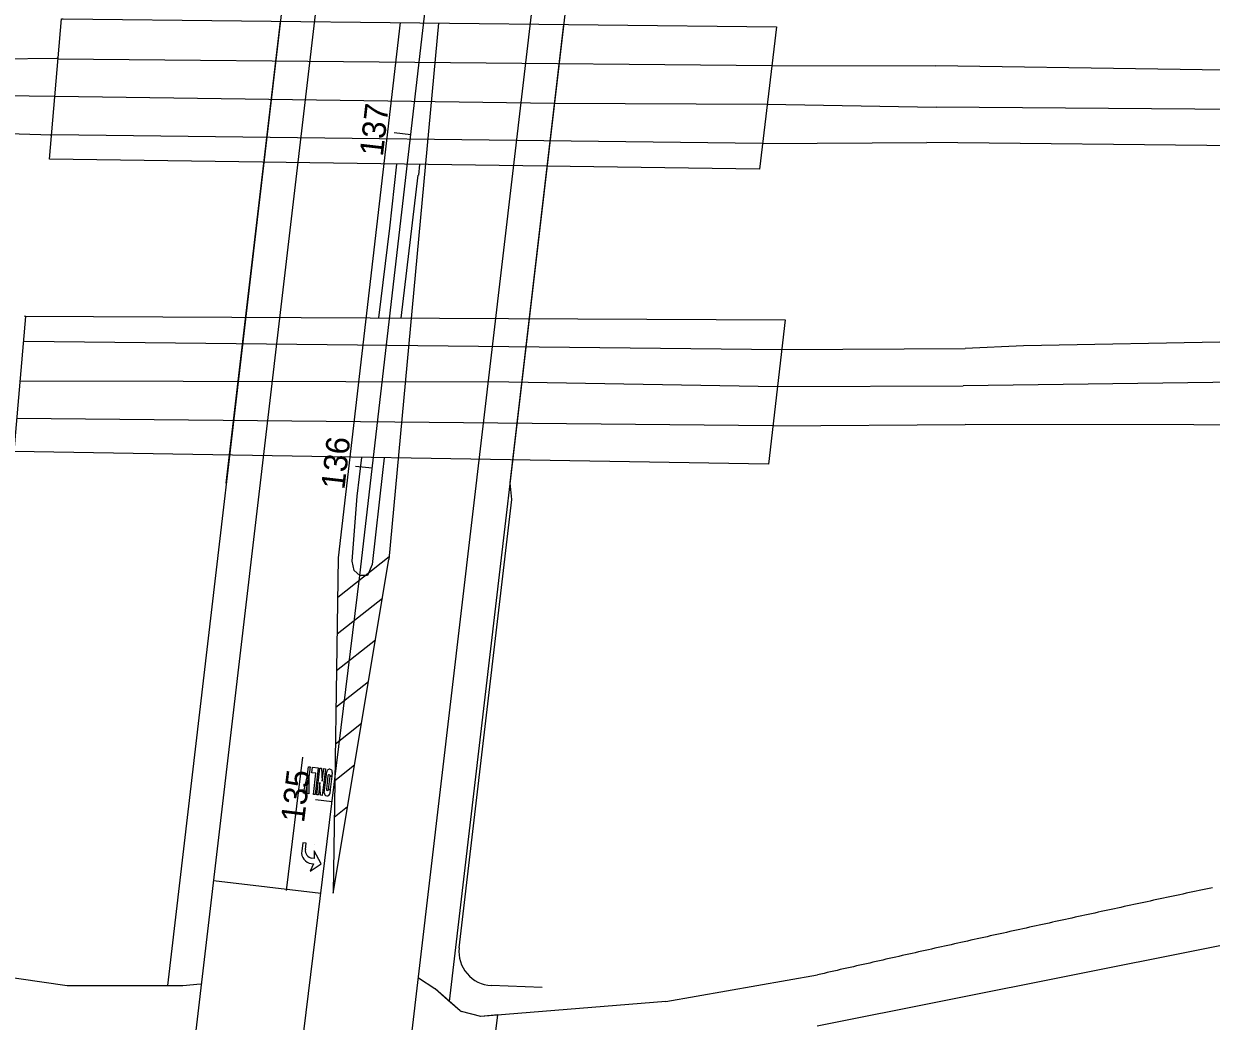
# Model space of a CAD drawing. Extents: x 2318076 to 2324211, y 613525 to 629939.
# Drawn here: x 2320472.4 to 2320826.1, y 628005.7 to 628302.7 of the extents above; entities that cross this region are included whole.
import ezdxf

# ---------------------------------------------------------------- set-up
doc = ezdxf.new("R2010")
doc.units = 0
for name, color, linetype in [('BR_X_Slab_Object', 7, 'Continuous'), ('GE_P_CL_50', 7, 'Continuous'), ('GE_X_CL_50', 7, 'Continuous'), ('PM_P_Cells', 7, 'Continuous'), ('PM_P_Channelizing_Line', 7, 'Continuous'), ('PM_P_CL_Double_Solid', 7, 'Continuous'), ('PM_P_Stop_Line', 7, 'Continuous'), ('PM_P_Transverse_Line', 7, 'Continuous'), ('PV_P_EOP', 7, 'Continuous'), ('PV_P_Shoulder', 7, 'Continuous'), ('RD_X_Concrete_Barrier', 7, 'Continuous'), ('RD_X_GR_Rt', 7, 'Continuous'), ('RS_Raster1', 7, 'Continuous'), ('TX_P_1', 7, 'Continuous')]:
    doc.layers.add(name, color=color, linetype=linetype)

msp = doc.modelspace()

# ---------------------------------------------------------------- linework, layer by layer
at = {"layer": 'BR_X_Slab_Object'}
for points in [[(2320484.11, 628304.16), (2320696.64, 628301.84), (2320691.49, 628259.41), (2320480.05, 628262.45), (2320483.63, 628304.22), (2320484.11, 628304.16)], [(2320472.62, 628215.62), (2320699.2, 628214.57), (2320694.19, 628171.55), (2320469.54, 628175.38), (2320473.07, 628215.6), (2320472.62, 628215.62)]]:
    msp.add_lwpolyline(points, dxfattribs=at)
at = {"layer": 'GE_P_CL_50'}
for p, q in [((2320587.68, 628269.7), (2320582.71, 628270.28)), ((2320576.2, 628170.36), (2320571.24, 628170.94)), ((2320564.24, 628071.08), (2320559.28, 628071.69))]:
    msp.add_line(p, q, dxfattribs=at)
msp.add_lwpolyline([(2320485.22, 627375.57), (2320502.11, 627520.92), (2320519.22, 627676.47), (2320531.82, 627783.89), (2320546.8, 627927.12), (2320554.45, 627991.34), (2320572.51, 628138.41), (2320649.52, 628804.84), (2320678.77, 629064.5), (2320690.76, 629163.78), (2320713.75, 629362.45), (2320725.26, 629461.78), (2320736.97, 629561.09), (2320748.4, 629660.43), (2320759.09, 629759.86), (2320769.62, 629859.3), (2320777.51, 629931.12), (2320778.25, 629937.84)], dxfattribs=at)
at = {"layer": 'GE_X_CL_50'}
for p, q in [((2320693.84, 628278.81), (2320744.17, 628277.94)), ((2320696.89, 628194.75), (2320752.2, 628194.93))]:
    msp.add_line(p, q, dxfattribs=at)
for points in [[(2318838.45, 628297.22), (2318989.13, 628295.38), (2319088.09, 628295.11), (2319168.95, 628294.58), (2319288.86, 628293.23), (2319411.65, 628291.27), (2319534.7, 628290.63), (2319653.02, 628288.28), (2319787.77, 628287.82), (2319899.47, 628286.31), (2320023.98, 628283.93), (2320152.65, 628284.01), (2320313.42, 628283.33), (2320481.66, 628281.19)], [(2320481.66, 628281.19), (2320630.42, 628279.04), (2320693.84, 628278.81)], [(2324211.2, 628237.88), (2324100.06, 628239.11), (2323887.64, 628240.84), (2323663.24, 628242.75), (2323428.01, 628246.39), (2323213.46, 628248.27), (2322983.92, 628250.37), (2322767.24, 628252.05), (2322547.46, 628255.46), (2322330.87, 628255.46), (2322180.02, 628258.17), (2321966.82, 628260.25), (2321752.93, 628261.56), (2321536.81, 628262.78), (2321340.76, 628266.62), (2321134.19, 628270.5), (2320911.42, 628276.64), (2320744.17, 628277.94)], [(2324209.54, 628169.05), (2324083.71, 628171.5), (2323932.07, 628172.99), (2323766.88, 628174.57), (2323590.27, 628175.99), (2323408.74, 628177.82), (2323205.61, 628179.86), (2322996.88, 628181.76), (2322795.55, 628183.99), (2322599.35, 628185.59), (2322419.03, 628185.84), (2322219.16, 628188.61), (2322096.17, 628189.9), (2321916.88, 628191.94), (2321753.71, 628193.94), (2321590.88, 628195.93), (2321431.73, 628197.42), (2321257.02, 628198.59), (2321067.83, 628197.06), (2320865.89, 628196.4), (2320752.2, 628194.93)], [(2320471.39, 628196.41), (2320616.88, 628196.07), (2320696.89, 628194.75)]]:
    msp.add_lwpolyline(points, dxfattribs=at)
at = {"layer": 'PM_P_Cells'}
for p, q in [((2320556.86, 628078.52), (2320557.21, 628081.5)), ((2320557.21, 628081.5), (2320557.71, 628081.44)), ((2320557.71, 628081.44), (2320557.36, 628078.46)), ((2320558.26, 628079.7), (2320558.46, 628081.35)), ((2320558.46, 628081.35), (2320560.11, 628081.16)), ((2320560.11, 628081.16), (2320559.16, 628073.21)), ((2320559.66, 628073.15), (2320560.61, 628081.1)), ((2320560.53, 628081.11), (2320560.53, 628081.11)), ((2320560.61, 628081.1), (2320561.1, 628081.04)), ((2320561.1, 628081.04), (2320561.32, 628077.24)), ((2320561.32, 628077.24), (2320561.77, 628080.96)), ((2320562.26, 628080.9), (2320561.32, 628072.96)), ((2320561.77, 628080.96), (2320562.26, 628080.9)), ((2320555.69, 628073.63), (2320556.86, 628078.52)), ((2320557.36, 628078.46), (2320557.34, 628073.43)), ((2320559.42, 628079.56), (2320558.26, 628079.7)), ((2320558.67, 628073.27), (2320559.42, 628079.56)), ((2320561.91, 628073.72), (2320562.66, 628080.01)), ((2320563.02, 628078.8), (2320562.55, 628074.82)), ((2320563.21, 628074.75), (2320563.68, 628078.72)), ((2320564.18, 628078.66), (2320563.68, 628078.72)), ((2320563.68, 628078.72), (2320564.18, 628078.66)), ((2320564.18, 628078.66), (2320563.7, 628074.69)), ((2320564.32, 628079.82), (2320564.18, 628078.66)), ((2320556.19, 628073.57), (2320555.69, 628073.63)), ((2320556.83, 628076.18), (2320556.19, 628073.57)), ((2320556.85, 628073.49), (2320556.83, 628076.18)), ((2320557.34, 628073.43), (2320556.85, 628073.49)), ((2320560.6, 628076.82), (2320560.16, 628073.09)), ((2320560.82, 628073.02), (2320560.6, 628076.82)), ((2320563.21, 628074.75), (2320563.7, 628074.69)), ((2320563.7, 628074.69), (2320563.21, 628074.75)), ((2320563.7, 628074.69), (2320563.57, 628073.53)), ((2320559.16, 628073.21), (2320558.67, 628073.27)), ((2320559.58, 628073.16), (2320559.58, 628073.16)), ((2320560.16, 628073.09), (2320559.66, 628073.15)), ((2320561.32, 628072.96), (2320560.82, 628073.02)), ((2320555.58, 628058.86), (2320555.21, 628056.41)), ((2320556.57, 628058.71), (2320555.58, 628058.86)), ((2320556.29, 628056.87), (2320556.57, 628058.71)), ((2320558.88, 628058.37), (2320558.88, 628058.37)), ((2320561.04, 628052.55), (2320558.92, 628056.42)), ((2320558.92, 628056.42), (2320558.92, 628054.16)), ((2320558.69, 628052.57), (2320557.7, 628050.45)), ((2320557.7, 628050.45), (2320561.04, 628052.55)), ((2320558.03, 628052.67), (2320558.69, 628052.57)), ((2320558.92, 628054.16), (2320558.23, 628054.26)), ((2320557.7, 628050.45), (2320557.7, 628050.45))]:
    msp.add_line(p, q, dxfattribs=at)
for centre, radius, start, end in [((2320563.49, 628079.92), 0.833, 353.2057, 173.2057), ((2320563.35, 628078.76), 0.333, 353.2057, 173.2057), ((2320562.74, 628073.63), 0.833, 173.2057, 353.2057), ((2320562.88, 628074.78), 0.333, 173.2057, 353.2057), ((2320558.46, 628055.92), 3.28, 171.5547, 262.4632), ((2320558.57, 628056.53), 2.3, 171.5547, 261.5547)]:
    msp.add_arc(centre, radius, start, end, dxfattribs=at)
at = {"layer": 'PM_P_Channelizing_Line'}
msp.add_lwpolyline([(2320550.68, 628044.66), (2320555.55, 628084.31)], dxfattribs=at)
at = {"layer": 'PM_P_CL_Double_Solid'}
for p, q in [((2320566.09, 628143.74), (2320564.56, 628043.85)), ((2320564.56, 628043.85), (2320581.17, 628143.24))]:
    msp.add_line(p, q, dxfattribs=at)
at = {"layer": 'PM_P_Stop_Line'}
msp.add_line((2320560.89, 628043.75), (2320528.92, 628047.49), dxfattribs=at)
at = {"layer": 'PM_P_Transverse_Line'}
for p, q in [((2320581.24, 628144), (2320565.91, 628131.86)), ((2320579.23, 628131.63), (2320565.74, 628120.95)), ((2320577.16, 628119.22), (2320565.58, 628110.05)), ((2320575.08, 628106.8), (2320565.41, 628099.14)), ((2320573.01, 628094.39), (2320565.24, 628088.24)), ((2320570.93, 628081.97), (2320565.07, 628077.33)), ((2320568.85, 628069.56), (2320564.9, 628066.43))]:
    msp.add_line(p, q, dxfattribs=at)
at = {"layer": 'PV_P_EOP'}
for p, q in [((2320590.74, 628574.92), (2320513.05, 627912.02)), ((2320576.7, 627905.37), (2320654.32, 628567.57)), ((2320584.51, 628303.06), (2320566.09, 628143.74)), ((2320595.94, 628302.94), (2320581.17, 628143.24)), ((2320594.89, 628015.41), (2320589.97, 628018.59)), ((2320602.43, 628008.79), (2320594.99, 628015.33)), ((2320608.54, 628007.18), (2320602.78, 628008.61)), ((2320613.63, 628007.58), (2320608.54, 628007.18))]:
    msp.add_line(p, q, dxfattribs=at)
msp.add_lwpolyline([(2320609.79, 627975.91), (2320611.27, 627988.34), (2320613.63, 628007.58)], dxfattribs=at)
for centre, start, end in [((2320594.44, 628014.71), 48.6772, 57.1121), ((2320602.98, 628009.42), 228.6772, 256.0413)]:
    msp.add_arc(centre, 0.833, start, end, dxfattribs=at)
at = {"layer": 'PV_P_Shoulder'}
for p, q in [((2320567.18, 628459.79), (2320515.22, 628016.39)), ((2320599.22, 628011.62), (2320651.77, 628459.98))]:
    msp.add_line(p, q, dxfattribs=at)
at = {"layer": 'RD_X_Concrete_Barrier'}
for p, q in [((2320532.74, 628165.9), (2320548.86, 628303.45)), ((2320617.32, 628166.06), (2320633.31, 628302.53)), ((2320590.26, 628260.87), (2320589.95, 628257.65)), ((2320589.78, 628257.63), (2320584.73, 628215.1))]:
    msp.add_line(p, q, dxfattribs=at)
for points in [[(2320578.2, 628215.13), (2320581.45, 628241.83), (2320583.5, 628260.96)], [(2320579.8, 628173.5), (2320579.27, 628169.07), (2320576.16, 628141.69), (2320574.82, 628138.47), (2320572.51, 628138.41), (2320570.8, 628139.9), (2320570.22, 628142.76), (2320571.74, 628162.06), (2320573.15, 628173.61)]]:
    msp.add_lwpolyline(points, dxfattribs=at)
at = {"layer": 'RD_X_GR_Rt'}
for p, q in [((2320617.74, 628161.06), (2320617.32, 628166.06)), ((2320602.09, 628027.57), (2320617.74, 628161.06)), ((2320626.8, 628015.81), (2320611.63, 628016.41))]:
    msp.add_line(p, q, dxfattribs=at)
msp.add_arc((2320612.03, 628026.4), 10, 173.3152, 267.7232, dxfattribs=at)
at = {"layer": 'RS_Raster1'}
for p, q in [((2320461.2, 628292.32), (2320482.62, 628292.44)), ((2320482.6, 628292.26), (2320695.24, 628290.34)), ((2320695.24, 628290.34), (2320743.98, 628290.21)), ((2320459.66, 628270.38), (2320480.66, 628269.62)), ((2320692.42, 628267.1), (2320480.67, 628269.63)), ((2320692.42, 628267.1), (2320741.34, 628267.39)), ((2320472.42, 628208.2), (2320698.17, 628205.7)), ((2320770.14, 628206.88), (2320752.78, 628205.99)), ((2320695.53, 628183.05), (2320470.4, 628185.22)), ((2320594.89, 628015.41), (2320590.03, 628018.55)), ((2320663.67, 628011.61), (2320708.82, 628019.53)), ((2320663.67, 628011.61), (2320608.54, 628007.18)), ((2320608.54, 628007.18), (2320602.78, 628008.61))]:
    msp.add_line(p, q, dxfattribs=at)
for points in [[(2321697.05, 628274.02), (2321509.24, 628275.49), (2321370.91, 628277.11), (2321223.2, 628279.67), (2321052.69, 628284.46), (2320876.34, 628288.23), (2320743.98, 628290.21)], [(2324210.96, 628226.01), (2324099.22, 628227.57), (2323922.84, 628229.43), (2323739.86, 628231.28), (2323551.5, 628233.43), (2323336.85, 628235.53), (2323118.39, 628237.8), (2322909.54, 628239.37), (2322678.89, 628242.27), (2322452.59, 628244.32), (2322252.25, 628245.65), (2322069.8, 628245.81), (2321869.81, 628248.03), (2321681.36, 628250.63), (2321451.01, 628251.29), (2321296.61, 628255.84), (2321123.18, 628260.35), (2320935.09, 628265.29), (2320741.34, 628267.39)], [(2324210.07, 628180.67), (2324126.99, 628181.82), (2323958.68, 628184.57), (2323765.72, 628185.78), (2323548.27, 628187.93), (2323298.91, 628189.99), (2323072.28, 628191.93), (2322817.32, 628194.08), (2322597.41, 628196.59), (2322367.08, 628198.37), (2322155.33, 628199.98), (2321962.28, 628202.76), (2321790.39, 628204.89), (2321604.43, 628210.03), (2321438.69, 628212.52), (2321272.37, 628212.78), (2321119.1, 628211.16), (2320939.43, 628209.93), (2320770.14, 628206.88)], [(2320698.17, 628205.7), (2320698.17, 628205.7), (2320752.83, 628205.99)], [(2319189.51, 628197.31), (2319278.1, 628191.01), (2319395.77, 628176.98), (2319442.58, 628171.23), (2319554.55, 628155.67), (2319664, 628139.56), (2319756.39, 628124.2), (2319834.01, 628113.24), (2319936.02, 628098.51), (2320027.26, 628084.66), (2320115.57, 628071.64), (2320199.48, 628059.37), (2320283.19, 628046.33), (2320384.46, 628030.93), (2320485.38, 628016.39)], [(2320695.53, 628183.05), (2320695.53, 628183.05), (2320752.78, 628183.39)], [(2321865.45, 628179.25), (2321679, 628181.71), (2321540.89, 628182.89), (2321384.45, 628185.57), (2321228.86, 628185.44), (2321052.77, 628183.94), (2320889, 628183.16), (2320752.78, 628183.39)], [(2321179.73, 628096.75), (2321032.45, 628067.95), (2320861.47, 628034.7), (2320708.68, 628004.26)], [(2320826.41, 628045.47), (2320825.44, 628045.27), (2320824.47, 628045.06), (2320823.49, 628044.85), (2320822.52, 628044.64), (2320821.55, 628044.44), (2320820.57, 628044.23), (2320819.6, 628044.02), (2320818.63, 628043.81), (2320817.65, 628043.6), (2320816.68, 628043.4), (2320815.71, 628043.19), (2320814.73, 628042.98), (2320813.76, 628042.77), (2320812.79, 628042.56), (2320811.81, 628042.35), (2320810.84, 628042.14), (2320809.87, 628041.93), (2320808.9, 628041.73), (2320807.92, 628041.52), (2320806.95, 628041.31), (2320805.98, 628041.1), (2320805, 628040.89), (2320804.03, 628040.68), (2320803.06, 628040.47), (2320802.09, 628040.26), (2320801.11, 628040.05), (2320800.14, 628039.84), (2320799.17, 628039.63), (2320798.19, 628039.42), (2320797.22, 628039.21), (2320796.25, 628038.99), (2320795.28, 628038.78), (2320794.3, 628038.57), (2320793.33, 628038.36), (2320792.36, 628038.15), (2320791.39, 628037.94), (2320790.41, 628037.73), (2320789.44, 628037.52), (2320788.47, 628037.3), (2320787.5, 628037.09), (2320786.52, 628036.88), (2320785.55, 628036.67), (2320784.58, 628036.46), (2320783.61, 628036.24), (2320782.63, 628036.03), (2320781.66, 628035.82), (2320780.69, 628035.61), (2320779.72, 628035.39), (2320778.75, 628035.18), (2320777.77, 628034.97), (2320776.8, 628034.75), (2320775.83, 628034.54), (2320774.86, 628034.33), (2320773.89, 628034.11), (2320772.91, 628033.9), (2320771.94, 628033.69), (2320770.97, 628033.47), (2320770, 628033.26), (2320769.03, 628033.04), (2320768.05, 628032.83), (2320767.08, 628032.61), (2320766.11, 628032.4), (2320765.14, 628032.19), (2320764.17, 628031.97), (2320763.19, 628031.76), (2320762.22, 628031.54), (2320761.25, 628031.33), (2320760.28, 628031.11), (2320759.31, 628030.89), (2320758.34, 628030.68), (2320757.36, 628030.46), (2320756.39, 628030.25), (2320755.42, 628030.03), (2320754.45, 628029.82), (2320753.48, 628029.6), (2320752.51, 628029.38), (2320751.54, 628029.17), (2320750.56, 628028.95), (2320749.59, 628028.73), (2320748.62, 628028.52), (2320747.65, 628028.3), (2320746.68, 628028.08), (2320745.71, 628027.87), (2320744.74, 628027.65), (2320743.77, 628027.43), (2320742.79, 628027.21), (2320741.82, 628027), (2320740.85, 628026.78), (2320739.88, 628026.56), (2320738.91, 628026.34), (2320737.94, 628026.13), (2320736.97, 628025.91), (2320736, 628025.69), (2320735.03, 628025.47), (2320734.05, 628025.25), (2320733.08, 628025.03), (2320732.11, 628024.82), (2320731.14, 628024.6), (2320730.17, 628024.38), (2320729.2, 628024.16), (2320728.23, 628023.94), (2320727.26, 628023.72), (2320726.29, 628023.5), (2320725.32, 628023.28), (2320724.35, 628023.06), (2320723.38, 628022.84), (2320722.41, 628022.62), (2320721.44, 628022.4), (2320720.46, 628022.18), (2320719.49, 628021.96), (2320718.52, 628021.74), (2320717.55, 628021.52), (2320716.58, 628021.3), (2320715.61, 628021.08), (2320714.64, 628020.86), (2320713.67, 628020.64), (2320712.7, 628020.42), (2320711.73, 628020.19), (2320710.76, 628019.97), (2320709.79, 628019.75), (2320708.82, 628019.53)], [(2320485.38, 628016.39), (2320494.26, 628016.39), (2320499.53, 628016.39), (2320508.04, 628016.39), (2320519.83, 628016.39), (2320525.1, 628016.85)], [(2320602.43, 628008.79), (2320598.76, 628012.02), (2320594.99, 628015.33)]]:
    msp.add_lwpolyline(points, dxfattribs=at)
for centre, start, end in [((2320594.44, 628014.71), 48.6772, 57.1121), ((2320602.98, 628009.42), 228.6772, 256.0413)]:
    msp.add_arc(centre, 0.833, start, end, dxfattribs=at)
at = {"layer": 'TX_P_1'}
for p, q in [((2320482.23, 628292.44), (2320482.62, 628292.44)), ((2320482.6, 628292.26), (2320482.32, 628292.44)), ((2320480.33, 628269.63), (2320480.67, 628269.63))]:
    msp.add_line(p, q, dxfattribs=at)

# ---------------------------------------------------------------- texts
at = {"layer": 'GE_P_CL_50'}
for s, rotation, p in [('137', 83.4084, (2320579.36, 628263.04)), ('136', 83.4084, (2320567.9, 628163.83)), ('135', 82.9992, (2320555.89, 628064.64))]:
    msp.add_text(s, height=7, rotation=rotation, dxfattribs=at).set_placement(p)

doc.saveas('drawing.dxf')
